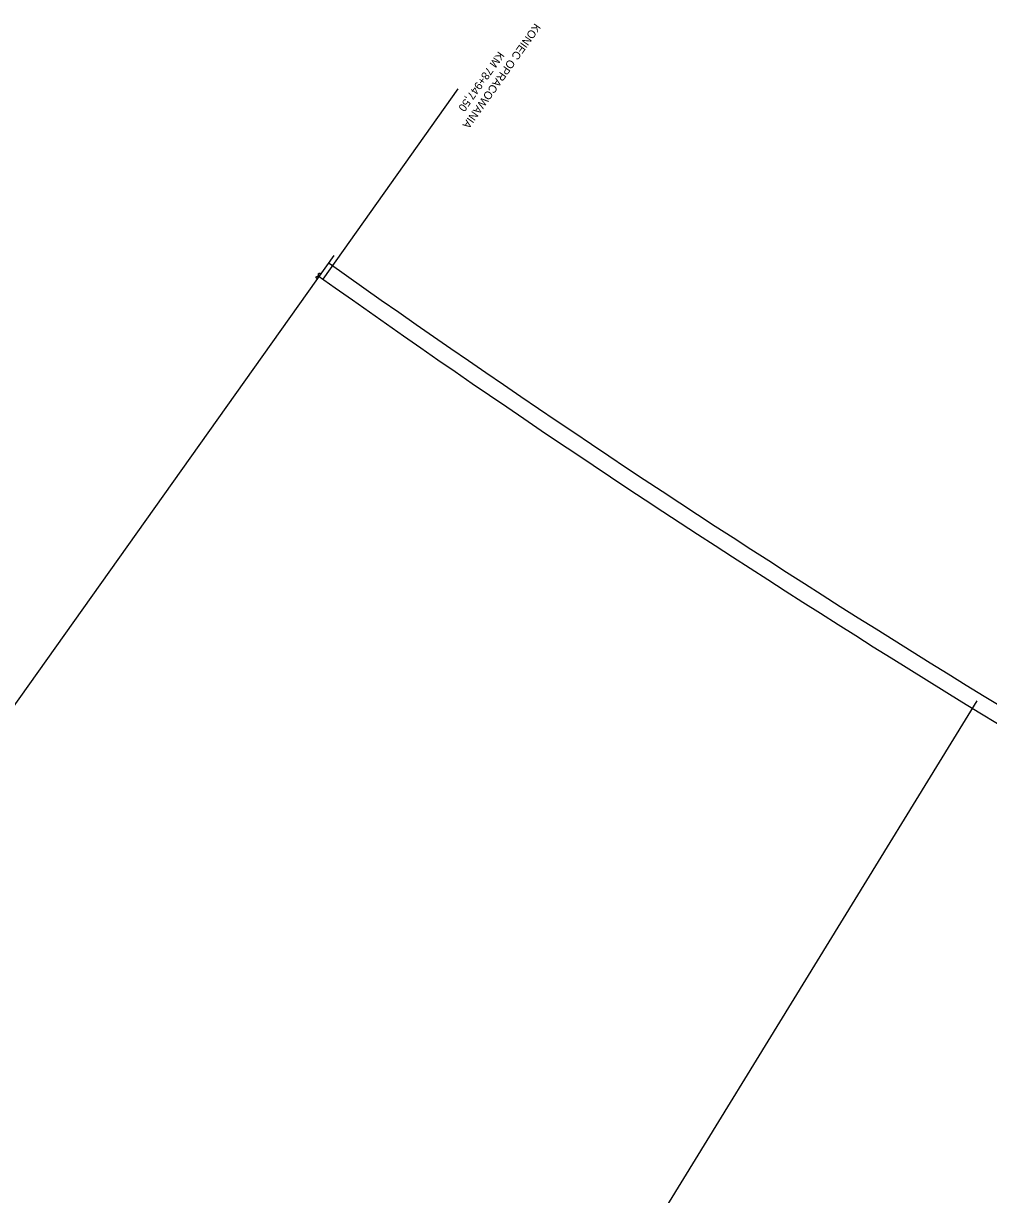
# Model space of a CAD drawing. Extents: x 6540402 to 6566579, y 5525343 to 5532423.
# Drawn here: x 6540899.9 to 6541141, y 5527497 to 5527789.7 of the extents above; entities that cross this region are included whole.
import ezdxf

# ---------------------------------------------------------------- set-up
doc = ezdxf.new("R2010")
doc.units = 0
for name, color, linetype in [('IR_ps_geometria', 7, 'Continuous'), ('TOR_PS_OPIS_T-hektometry projektowane', 7, 'Continuous'), ('TOR_PS_OPIS_T-opisy dodatkowe', 7, 'Continuous'), ('TOR_PS_T-tory projektowane', 7, 'Continuous'), ('TOR_RAMKI-ramka+tabelka 2', 7, 'Continuous')]:
    doc.layers.add(name, color=color, linetype=linetype)

msp = doc.modelspace()

# ---------------------------------------------------------------- linework, layer by layer
at = {"layer": 'IR_ps_geometria'}
msp.add_lwpolyline([(6540973.56, 5527726.59), (6540973.41, 5527726.39), (6540973.44, 5527726.37), (6540973.46, 5527726.34), (6540973.48, 5527726.32), (6540973.5, 5527726.29), (6540973.51, 5527726.26), (6540973.52, 5527726.23), (6540973.52, 5527726.19), (6540973.52, 5527726.16), (6540973.51, 5527726.13), (6540973.5, 5527726.1), (6540973.49, 5527726.07), (6540973.47, 5527726.04), (6540973.45, 5527726.01), (6540973.43, 5527725.99), (6540973.4, 5527725.97), (6540973.37, 5527725.96), (6540973.34, 5527725.95), (6540973.31, 5527725.94), (6540973.28, 5527725.93), (6540973.25, 5527725.94), (6540973.21, 5527725.94), (6540973.18, 5527725.95), (6540973.15, 5527725.96), (6540973.12, 5527725.98), (6540973.1, 5527726), (6540973.08, 5527726.02), (6540973.06, 5527726.05), (6540973.04, 5527726.08), (6540973.03, 5527726.11), (6540973.02, 5527726.14), (6540973.02, 5527726.17), (6540973.02, 5527726.21), (6540973.02, 5527726.24), (6540973.03, 5527726.27), (6540973.05, 5527726.3), (6540973.06, 5527726.33), (6540973.09, 5527726.35), (6540973.11, 5527726.38), (6540973.14, 5527726.4), (6540973.16, 5527726.41), (6540973.2, 5527726.42), (6540973.23, 5527726.43), (6540973.26, 5527726.43), (6540973.29, 5527726.43), (6540973.32, 5527726.43), (6540973.36, 5527726.42), (6540973.39, 5527726.41), (6540973.41, 5527726.39), (6540973.7, 5527726.8), (6540973.68, 5527726.82), (6540973.66, 5527726.84), (6540973.64, 5527726.87), (6540973.62, 5527726.9), (6540973.61, 5527726.93), (6540973.6, 5527726.96), (6540973.6, 5527726.99), (6540973.6, 5527727.02), (6540973.6, 5527727.06), (6540973.61, 5527727.09), (6540973.63, 5527727.12), (6540973.64, 5527727.14), (6540973.66, 5527727.17), (6540973.69, 5527727.19), (6540973.72, 5527727.21), (6540973.74, 5527727.23), (6540973.77, 5527727.24), (6540973.81, 5527727.25), (6540973.84, 5527727.25), (6540973.87, 5527727.25), (6540973.9, 5527727.24), (6540973.94, 5527727.23), (6540973.96, 5527727.22), (6540973.99, 5527727.2), (6540974.02, 5527727.18), (6540974.04, 5527727.16), (6540974.06, 5527727.13), (6540974.08, 5527727.1), (6540974.09, 5527727.07), (6540974.09, 5527727.04), (6540974.1, 5527727.01), (6540974.1, 5527726.98), (6540974.09, 5527726.94), (6540974.08, 5527726.91), (6540974.07, 5527726.88), (6540974.05, 5527726.85), (6540974.03, 5527726.83), (6540974.01, 5527726.81), (6540973.98, 5527726.79), (6540973.95, 5527726.77), (6540973.92, 5527726.76), (6540973.89, 5527726.75), (6540973.86, 5527726.75), (6540973.82, 5527726.75), (6540973.79, 5527726.76), (6540973.76, 5527726.76), (6540973.73, 5527726.78), (6540973.7, 5527726.8)], close=True, dxfattribs=at)
msp.add_lwpolyline([(6540973.56, 5527726.59), (6540973.41, 5527726.39), (6540973.44, 5527726.37), (6540973.46, 5527726.34), (6540973.48, 5527726.32), (6540973.5, 5527726.29), (6540973.51, 5527726.26), (6540973.52, 5527726.23), (6540973.52, 5527726.19), (6540973.52, 5527726.16), (6540973.51, 5527726.13), (6540973.5, 5527726.1), (6540973.49, 5527726.07), (6540973.47, 5527726.04), (6540973.45, 5527726.01), (6540973.43, 5527725.99), (6540973.4, 5527725.97), (6540973.37, 5527725.96), (6540973.34, 5527725.95), (6540973.31, 5527725.94), (6540973.28, 5527725.93), (6540973.25, 5527725.94), (6540973.21, 5527725.94), (6540973.18, 5527725.95), (6540973.15, 5527725.96), (6540973.12, 5527725.98), (6540973.1, 5527726), (6540973.08, 5527726.02), (6540973.06, 5527726.05), (6540973.04, 5527726.08), (6540973.03, 5527726.11), (6540973.02, 5527726.14), (6540973.02, 5527726.17), (6540973.02, 5527726.21), (6540973.02, 5527726.24), (6540973.03, 5527726.27), (6540973.05, 5527726.3), (6540973.06, 5527726.33), (6540973.09, 5527726.35), (6540973.11, 5527726.38), (6540973.14, 5527726.4), (6540973.16, 5527726.41), (6540973.2, 5527726.42), (6540973.23, 5527726.43), (6540973.26, 5527726.43), (6540973.29, 5527726.43), (6540973.32, 5527726.43), (6540973.36, 5527726.42), (6540973.39, 5527726.41), (6540973.41, 5527726.39), (6540973.7, 5527726.8), (6540973.68, 5527726.82), (6540973.66, 5527726.84), (6540973.64, 5527726.87), (6540973.62, 5527726.9), (6540973.61, 5527726.93), (6540973.6, 5527726.96), (6540973.6, 5527726.99), (6540973.6, 5527727.02), (6540973.6, 5527727.06), (6540973.61, 5527727.09), (6540973.63, 5527727.12), (6540973.64, 5527727.14), (6540973.66, 5527727.17), (6540973.69, 5527727.19), (6540973.72, 5527727.21), (6540973.74, 5527727.23), (6540973.77, 5527727.24), (6540973.81, 5527727.25), (6540973.84, 5527727.25), (6540973.87, 5527727.25), (6540973.9, 5527727.24), (6540973.94, 5527727.23), (6540973.96, 5527727.22), (6540973.99, 5527727.2), (6540974.02, 5527727.18), (6540974.04, 5527727.16), (6540974.06, 5527727.13), (6540974.08, 5527727.1), (6540974.09, 5527727.07), (6540974.09, 5527727.04), (6540974.1, 5527727.01), (6540974.1, 5527726.98), (6540974.09, 5527726.94), (6540974.08, 5527726.91), (6540974.07, 5527726.88), (6540974.05, 5527726.85), (6540974.03, 5527726.83), (6540974.01, 5527726.81), (6540973.98, 5527726.79), (6540973.95, 5527726.77), (6540973.92, 5527726.76), (6540973.89, 5527726.75), (6540973.86, 5527726.75), (6540973.82, 5527726.75), (6540973.79, 5527726.76), (6540973.76, 5527726.76), (6540973.73, 5527726.78), (6540973.7, 5527726.8)], close=True, dxfattribs=at)
msp.add_lwpolyline([(6540973.56, 5527726.59), (6540973.41, 5527726.39), (6540973.44, 5527726.37), (6540973.46, 5527726.34), (6540973.48, 5527726.32), (6540973.5, 5527726.29), (6540973.51, 5527726.26), (6540973.52, 5527726.23), (6540973.52, 5527726.19), (6540973.52, 5527726.16), (6540973.51, 5527726.13), (6540973.5, 5527726.1), (6540973.49, 5527726.07), (6540973.47, 5527726.04), (6540973.45, 5527726.01), (6540973.43, 5527725.99), (6540973.4, 5527725.97), (6540973.37, 5527725.96), (6540973.34, 5527725.95), (6540973.31, 5527725.94), (6540973.28, 5527725.93), (6540973.25, 5527725.94), (6540973.21, 5527725.94), (6540973.18, 5527725.95), (6540973.15, 5527725.96), (6540973.12, 5527725.98), (6540973.1, 5527726), (6540973.08, 5527726.02), (6540973.06, 5527726.05), (6540973.04, 5527726.08), (6540973.03, 5527726.11), (6540973.02, 5527726.14), (6540973.02, 5527726.17), (6540973.02, 5527726.21), (6540973.02, 5527726.24), (6540973.03, 5527726.27), (6540973.05, 5527726.3), (6540973.06, 5527726.33), (6540973.09, 5527726.35), (6540973.11, 5527726.38), (6540973.14, 5527726.4), (6540973.16, 5527726.41), (6540973.2, 5527726.42), (6540973.23, 5527726.43), (6540973.26, 5527726.43), (6540973.29, 5527726.43), (6540973.32, 5527726.43), (6540973.36, 5527726.42), (6540973.39, 5527726.41), (6540973.41, 5527726.39), (6540973.7, 5527726.8), (6540973.68, 5527726.82), (6540973.66, 5527726.84), (6540973.64, 5527726.87), (6540973.62, 5527726.9), (6540973.61, 5527726.93), (6540973.6, 5527726.96), (6540973.6, 5527726.99), (6540973.6, 5527727.02), (6540973.6, 5527727.06), (6540973.61, 5527727.09), (6540973.63, 5527727.12), (6540973.64, 5527727.14), (6540973.66, 5527727.17), (6540973.69, 5527727.19), (6540973.72, 5527727.21), (6540973.74, 5527727.23), (6540973.77, 5527727.24), (6540973.81, 5527727.25), (6540973.84, 5527727.25), (6540973.87, 5527727.25), (6540973.9, 5527727.24), (6540973.94, 5527727.23), (6540973.96, 5527727.22), (6540973.99, 5527727.2), (6540974.02, 5527727.18), (6540974.04, 5527727.16), (6540974.06, 5527727.13), (6540974.08, 5527727.1), (6540974.09, 5527727.07), (6540974.09, 5527727.04), (6540974.1, 5527727.01), (6540974.1, 5527726.98), (6540974.09, 5527726.94), (6540974.08, 5527726.91), (6540974.07, 5527726.88), (6540974.05, 5527726.85), (6540974.03, 5527726.83), (6540974.01, 5527726.81), (6540973.98, 5527726.79), (6540973.95, 5527726.77), (6540973.92, 5527726.76), (6540973.89, 5527726.75), (6540973.86, 5527726.75), (6540973.82, 5527726.75), (6540973.79, 5527726.76), (6540973.76, 5527726.76), (6540973.73, 5527726.78), (6540973.7, 5527726.8)], close=True, dxfattribs=at)
msp.add_lwpolyline([(6540973.56, 5527726.59), (6540973.41, 5527726.39), (6540973.44, 5527726.37), (6540973.46, 5527726.34), (6540973.48, 5527726.32), (6540973.5, 5527726.29), (6540973.51, 5527726.26), (6540973.52, 5527726.23), (6540973.52, 5527726.19), (6540973.52, 5527726.16), (6540973.51, 5527726.13), (6540973.5, 5527726.1), (6540973.49, 5527726.07), (6540973.47, 5527726.04), (6540973.45, 5527726.01), (6540973.43, 5527725.99), (6540973.4, 5527725.97), (6540973.37, 5527725.96), (6540973.34, 5527725.95), (6540973.31, 5527725.94), (6540973.28, 5527725.93), (6540973.25, 5527725.94), (6540973.21, 5527725.94), (6540973.18, 5527725.95), (6540973.15, 5527725.96), (6540973.12, 5527725.98), (6540973.1, 5527726), (6540973.08, 5527726.02), (6540973.06, 5527726.05), (6540973.04, 5527726.08), (6540973.03, 5527726.11), (6540973.02, 5527726.14), (6540973.02, 5527726.17), (6540973.02, 5527726.21), (6540973.02, 5527726.24), (6540973.03, 5527726.27), (6540973.05, 5527726.3), (6540973.06, 5527726.33), (6540973.09, 5527726.35), (6540973.11, 5527726.38), (6540973.14, 5527726.4), (6540973.16, 5527726.41), (6540973.2, 5527726.42), (6540973.23, 5527726.43), (6540973.26, 5527726.43), (6540973.29, 5527726.43), (6540973.32, 5527726.43), (6540973.36, 5527726.42), (6540973.39, 5527726.41), (6540973.41, 5527726.39), (6540973.7, 5527726.8), (6540973.68, 5527726.82), (6540973.66, 5527726.84), (6540973.64, 5527726.87), (6540973.62, 5527726.9), (6540973.61, 5527726.93), (6540973.6, 5527726.96), (6540973.6, 5527726.99), (6540973.6, 5527727.02), (6540973.6, 5527727.06), (6540973.61, 5527727.09), (6540973.63, 5527727.12), (6540973.64, 5527727.14), (6540973.66, 5527727.17), (6540973.69, 5527727.19), (6540973.72, 5527727.21), (6540973.74, 5527727.23), (6540973.77, 5527727.24), (6540973.81, 5527727.25), (6540973.84, 5527727.25), (6540973.87, 5527727.25), (6540973.9, 5527727.24), (6540973.94, 5527727.23), (6540973.96, 5527727.22), (6540973.99, 5527727.2), (6540974.02, 5527727.18), (6540974.04, 5527727.16), (6540974.06, 5527727.13), (6540974.08, 5527727.1), (6540974.09, 5527727.07), (6540974.09, 5527727.04), (6540974.1, 5527727.01), (6540974.1, 5527726.98), (6540974.09, 5527726.94), (6540974.08, 5527726.91), (6540974.07, 5527726.88), (6540974.05, 5527726.85), (6540974.03, 5527726.83), (6540974.01, 5527726.81), (6540973.98, 5527726.79), (6540973.95, 5527726.77), (6540973.92, 5527726.76), (6540973.89, 5527726.75), (6540973.86, 5527726.75), (6540973.82, 5527726.75), (6540973.79, 5527726.76), (6540973.76, 5527726.76), (6540973.73, 5527726.78), (6540973.7, 5527726.8)], close=True, dxfattribs=at)
at = {"layer": 'TOR_PS_OPIS_T-hektometry projektowane'}
msp.add_lwpolyline([(6540977.45, 5527731.67), (6540533.82, 5527107.21)], dxfattribs=at)
at = {"layer": 'TOR_PS_OPIS_T-opisy dodatkowe'}
msp.add_line((6541138.09, 5527620.36), (6540748.25, 5526985.51), dxfattribs=at)
at = {"layer": 'TOR_PS_T-tory projektowane'}
for centre, radius, start, end in [((6542673.04, 5530118.43), 2930, 234.61315, 241.24998), ((6542664.96, 5530106.83), 2920, 234.60229, 241.14886)]:
    msp.add_arc(centre, radius, start, end, dxfattribs=at)
at = {"layer": 'TOR_RAMKI-ramka+tabelka 2'}
msp.add_line((6540974.76, 5527725.74), (6541008.51, 5527773.29), dxfattribs=at)

# ---------------------------------------------------------------- texts
for s, p in [('KONIEC OPRACOWANIA', (6541027.63, 5527789.85)), ('KM 78+947,50', (6541018.55, 5527782.82))]:
    msp.add_text(s, height=2, rotation=234.6363, dxfattribs=at).set_placement(p)

doc.saveas('drawing.dxf')
